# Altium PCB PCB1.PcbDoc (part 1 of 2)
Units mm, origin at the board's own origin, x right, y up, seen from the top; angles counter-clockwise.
Board outline 100 x 100 mm, 4 copper layers (Top Layer, Layer 1, Layer 2, Bottom Layer), stack 1.578 mm thick; 186 components, 85 nets, 396 pads, 143 vias.
Unrouted connection lines stored in the file: 19.
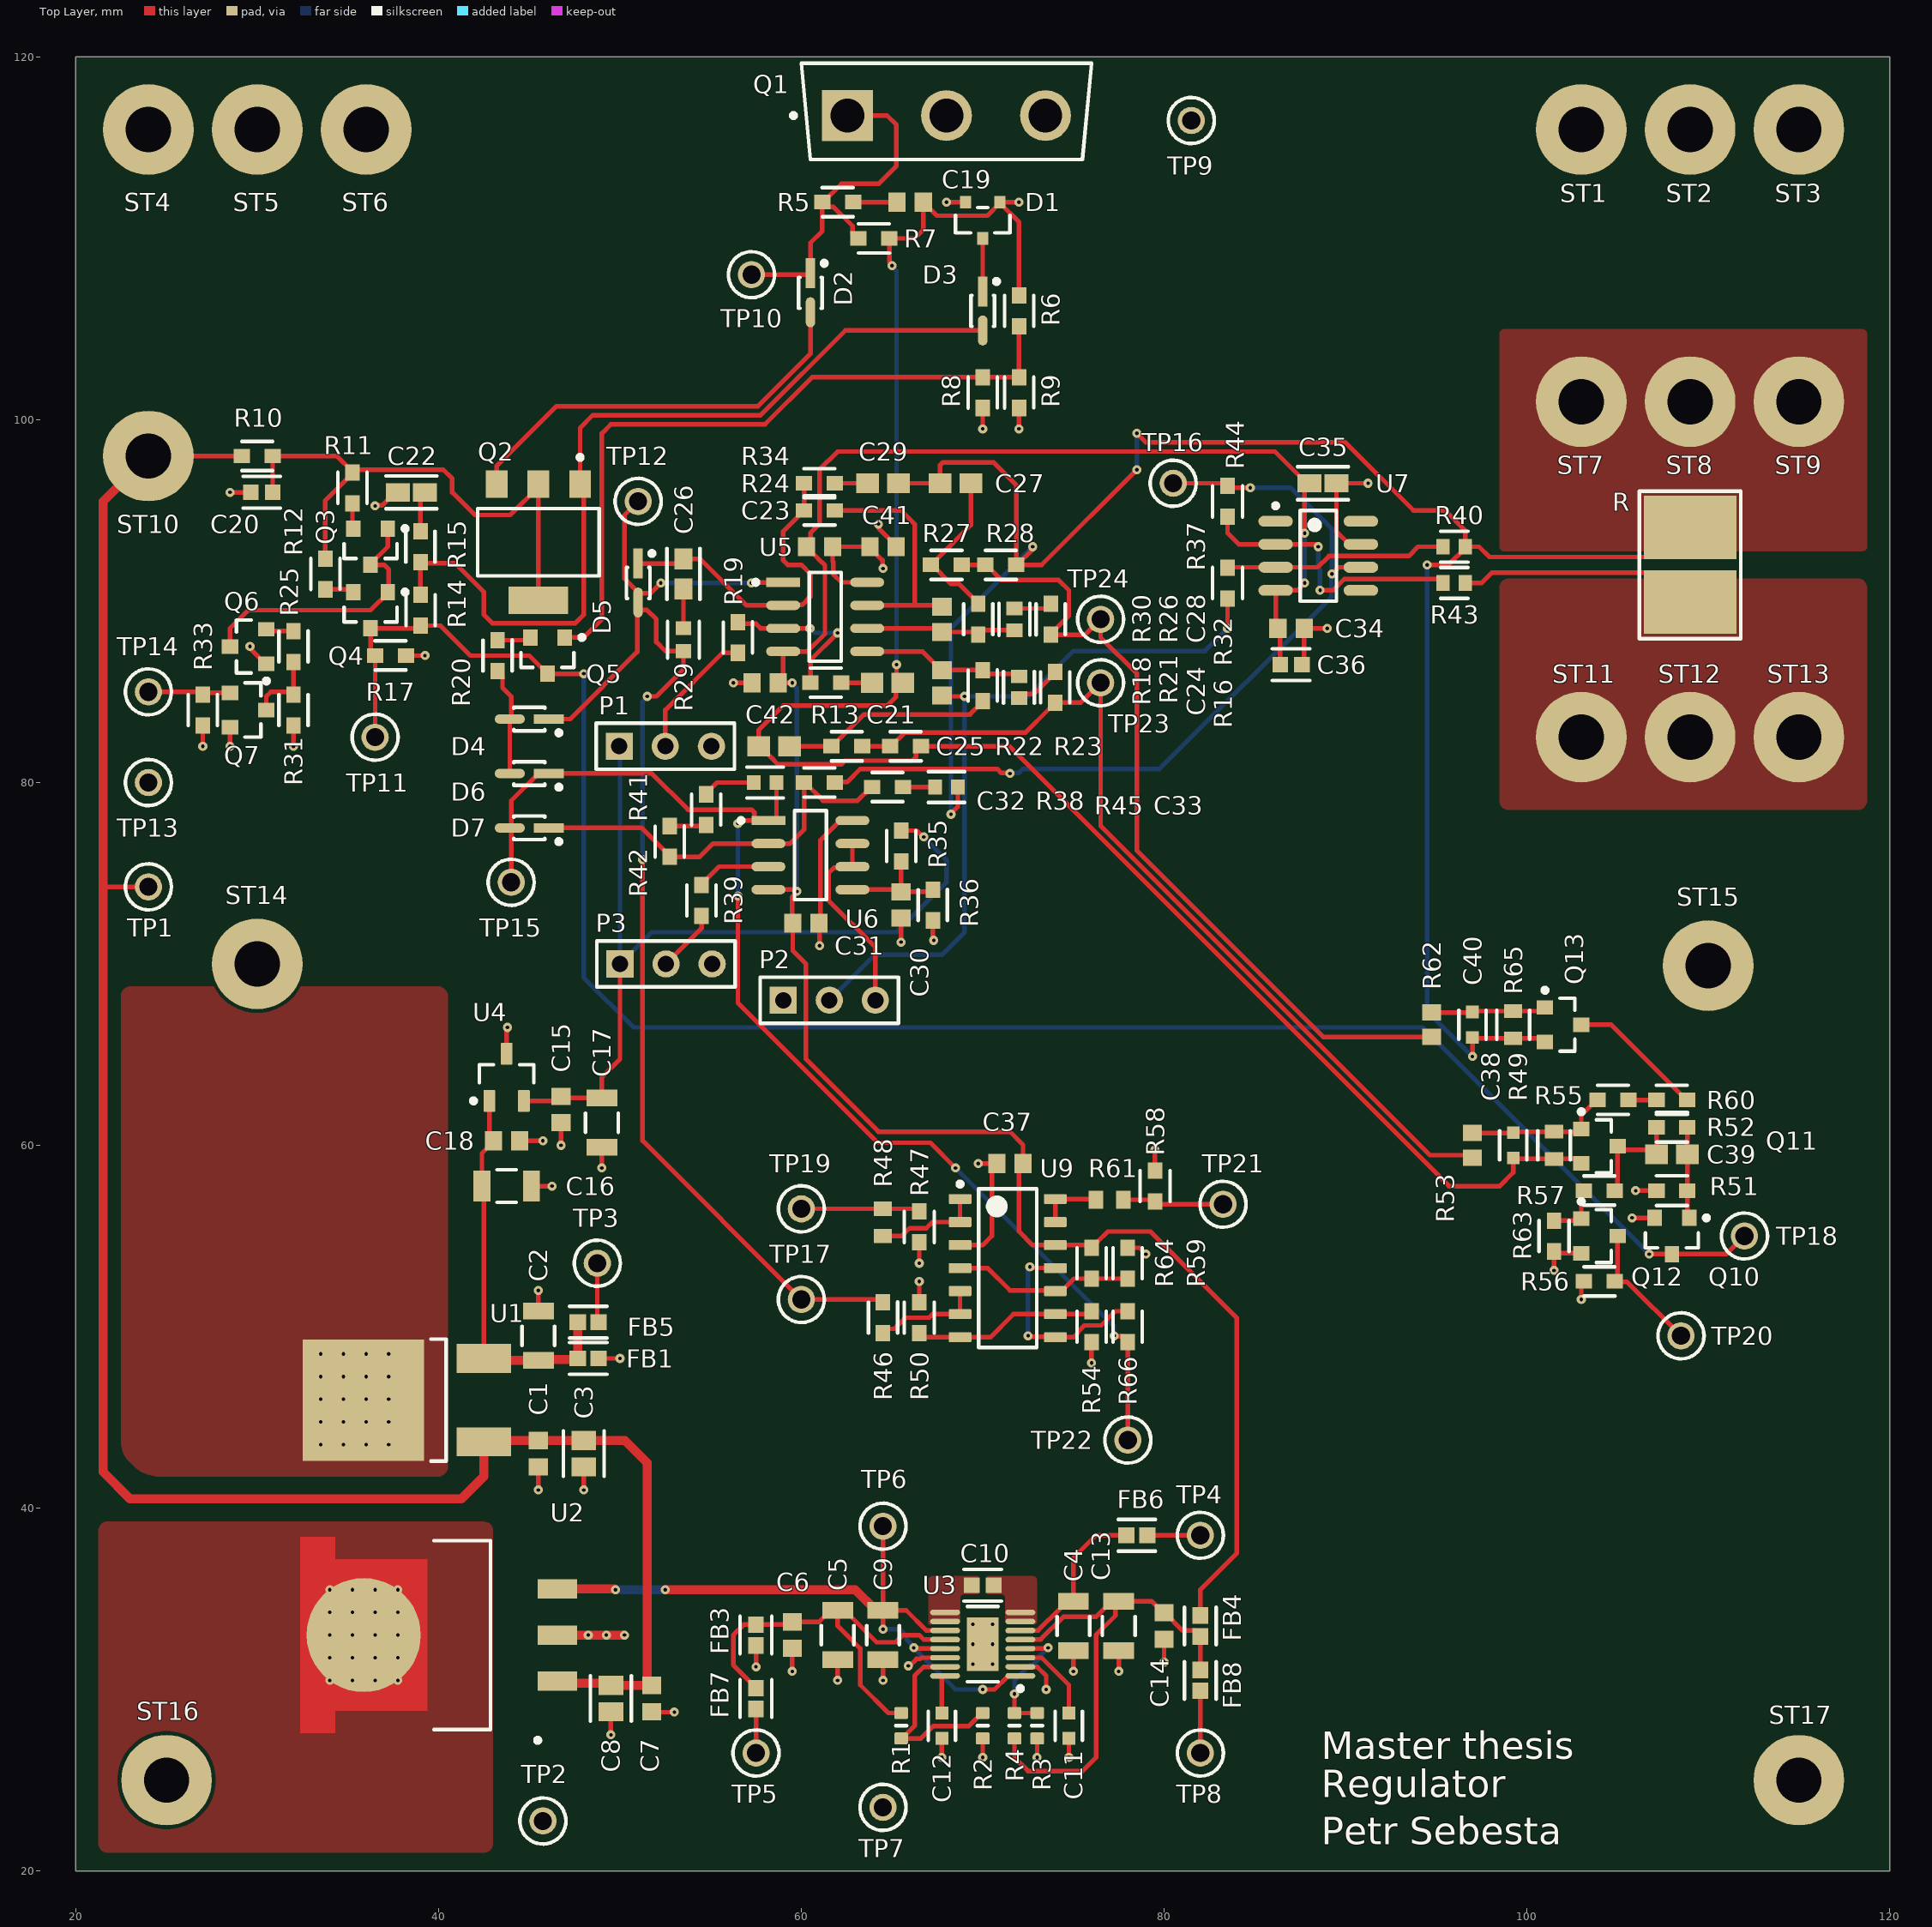
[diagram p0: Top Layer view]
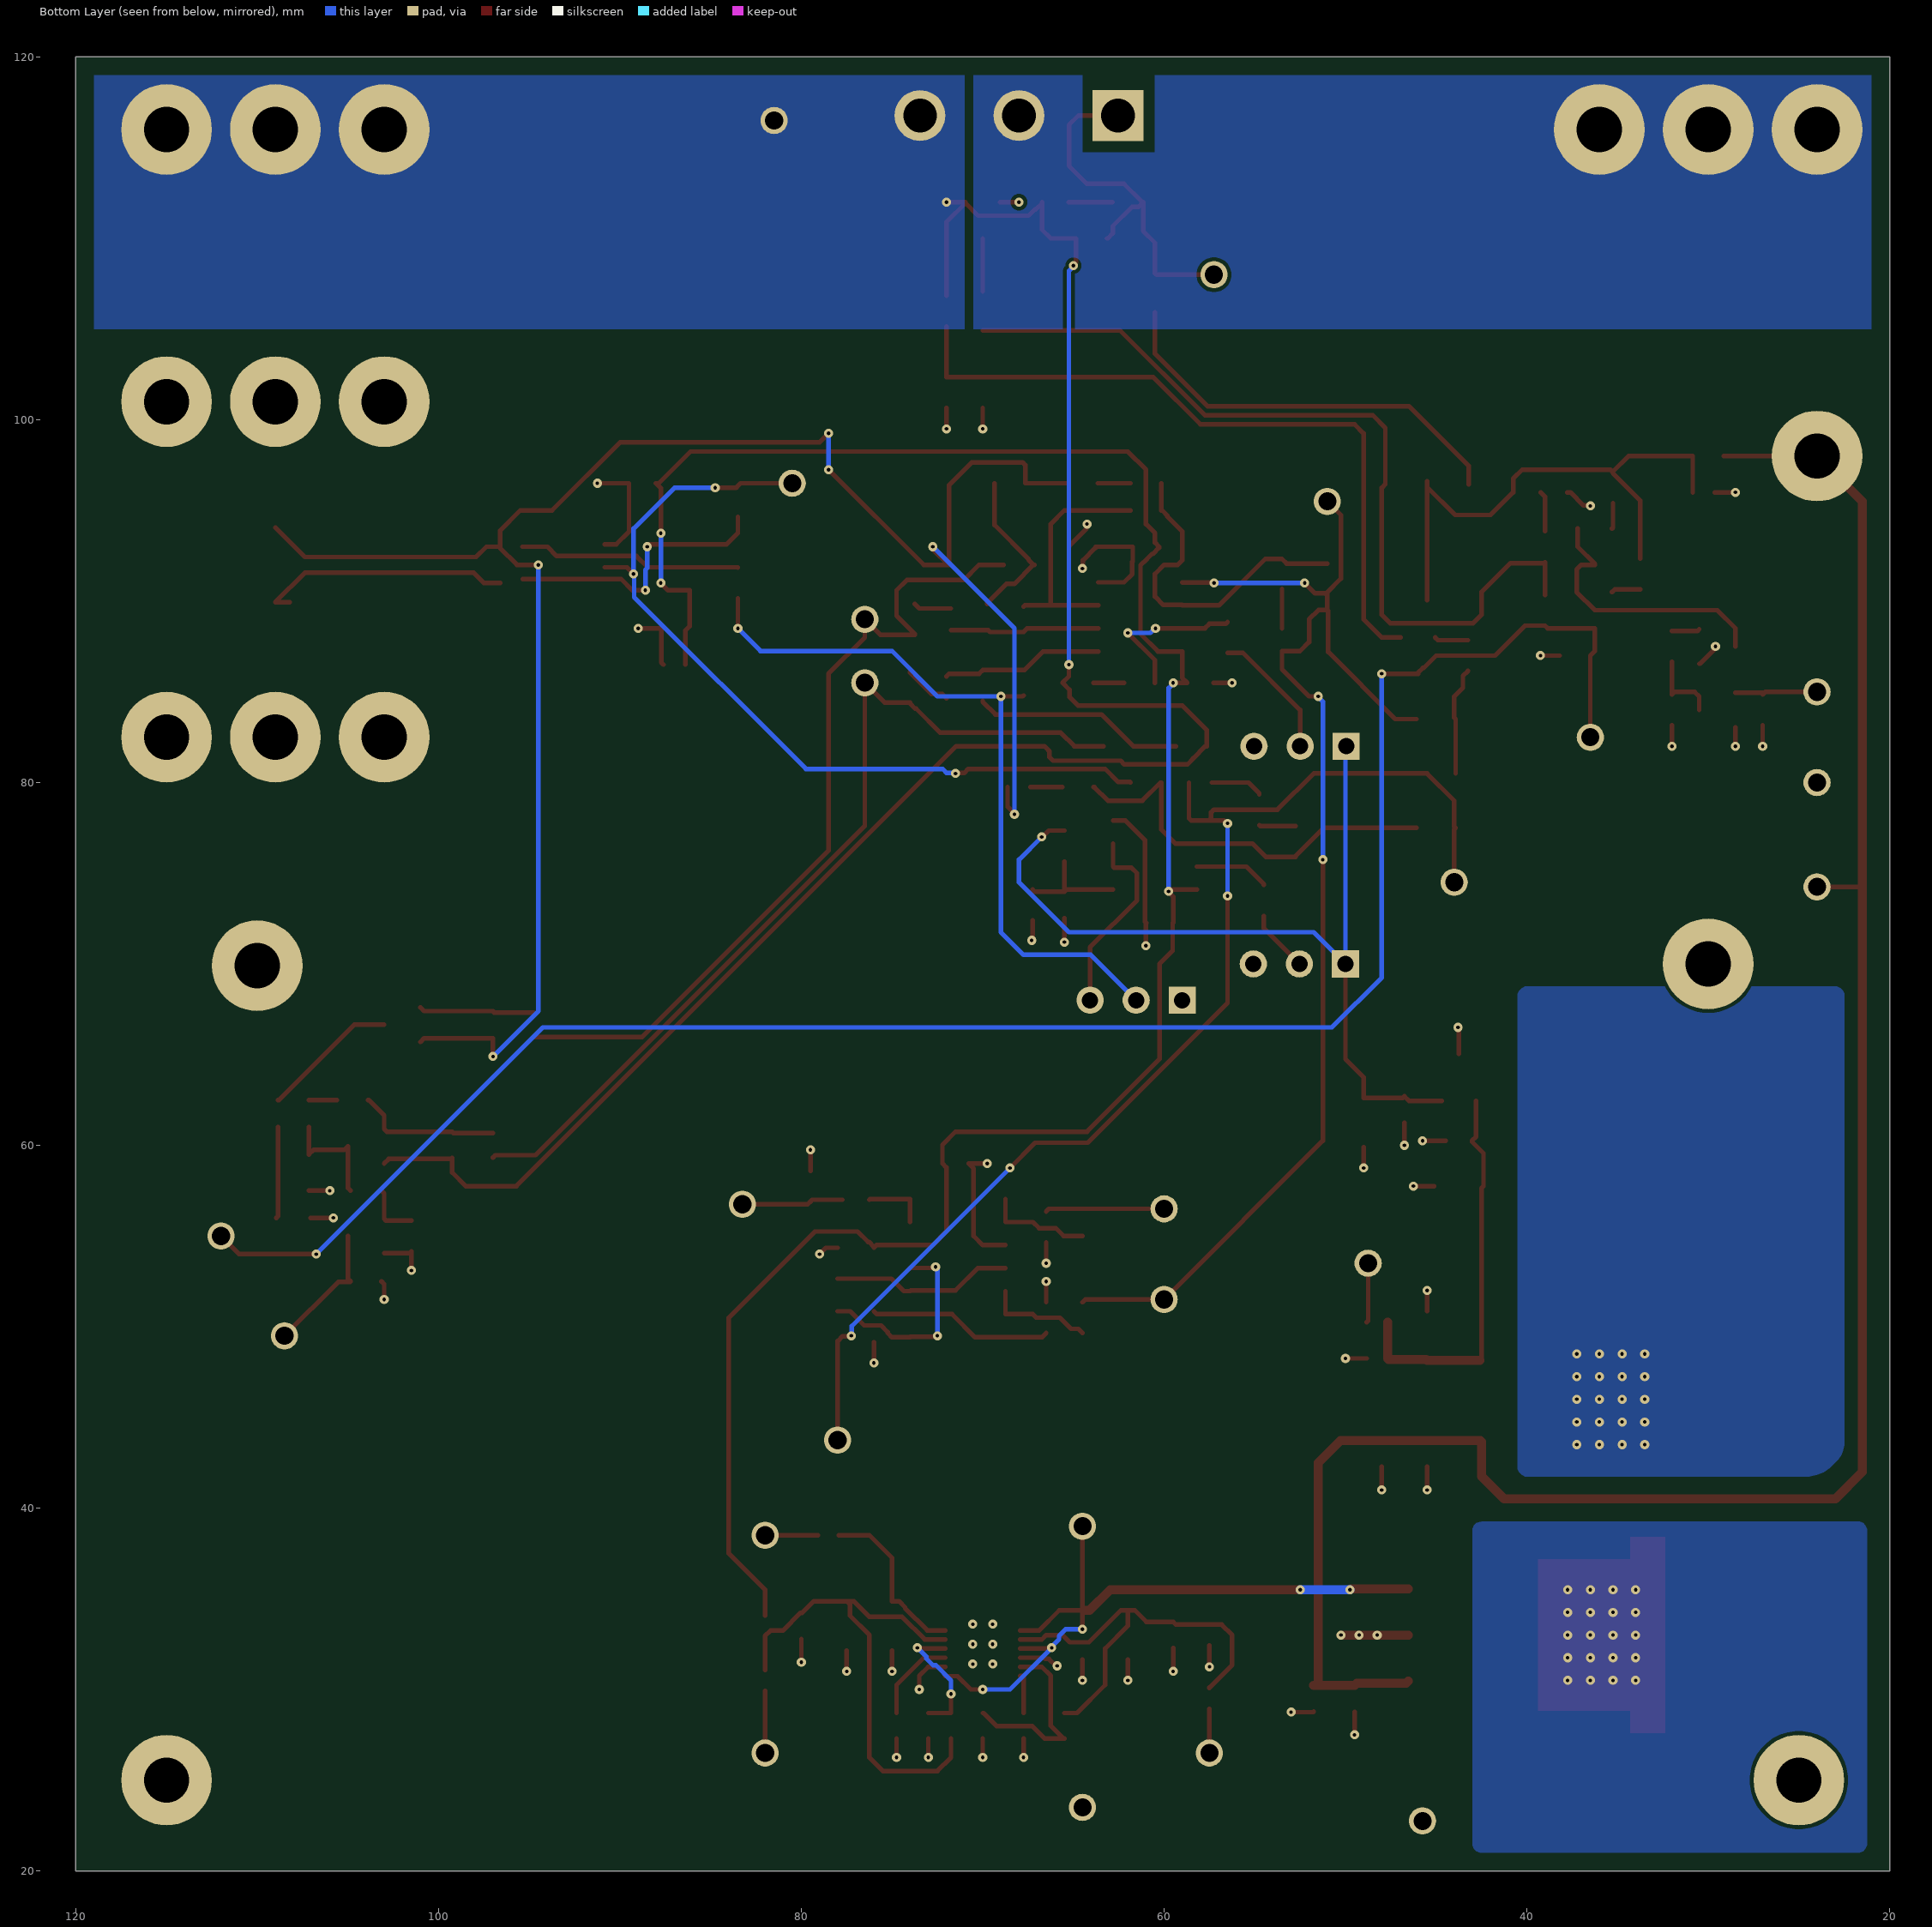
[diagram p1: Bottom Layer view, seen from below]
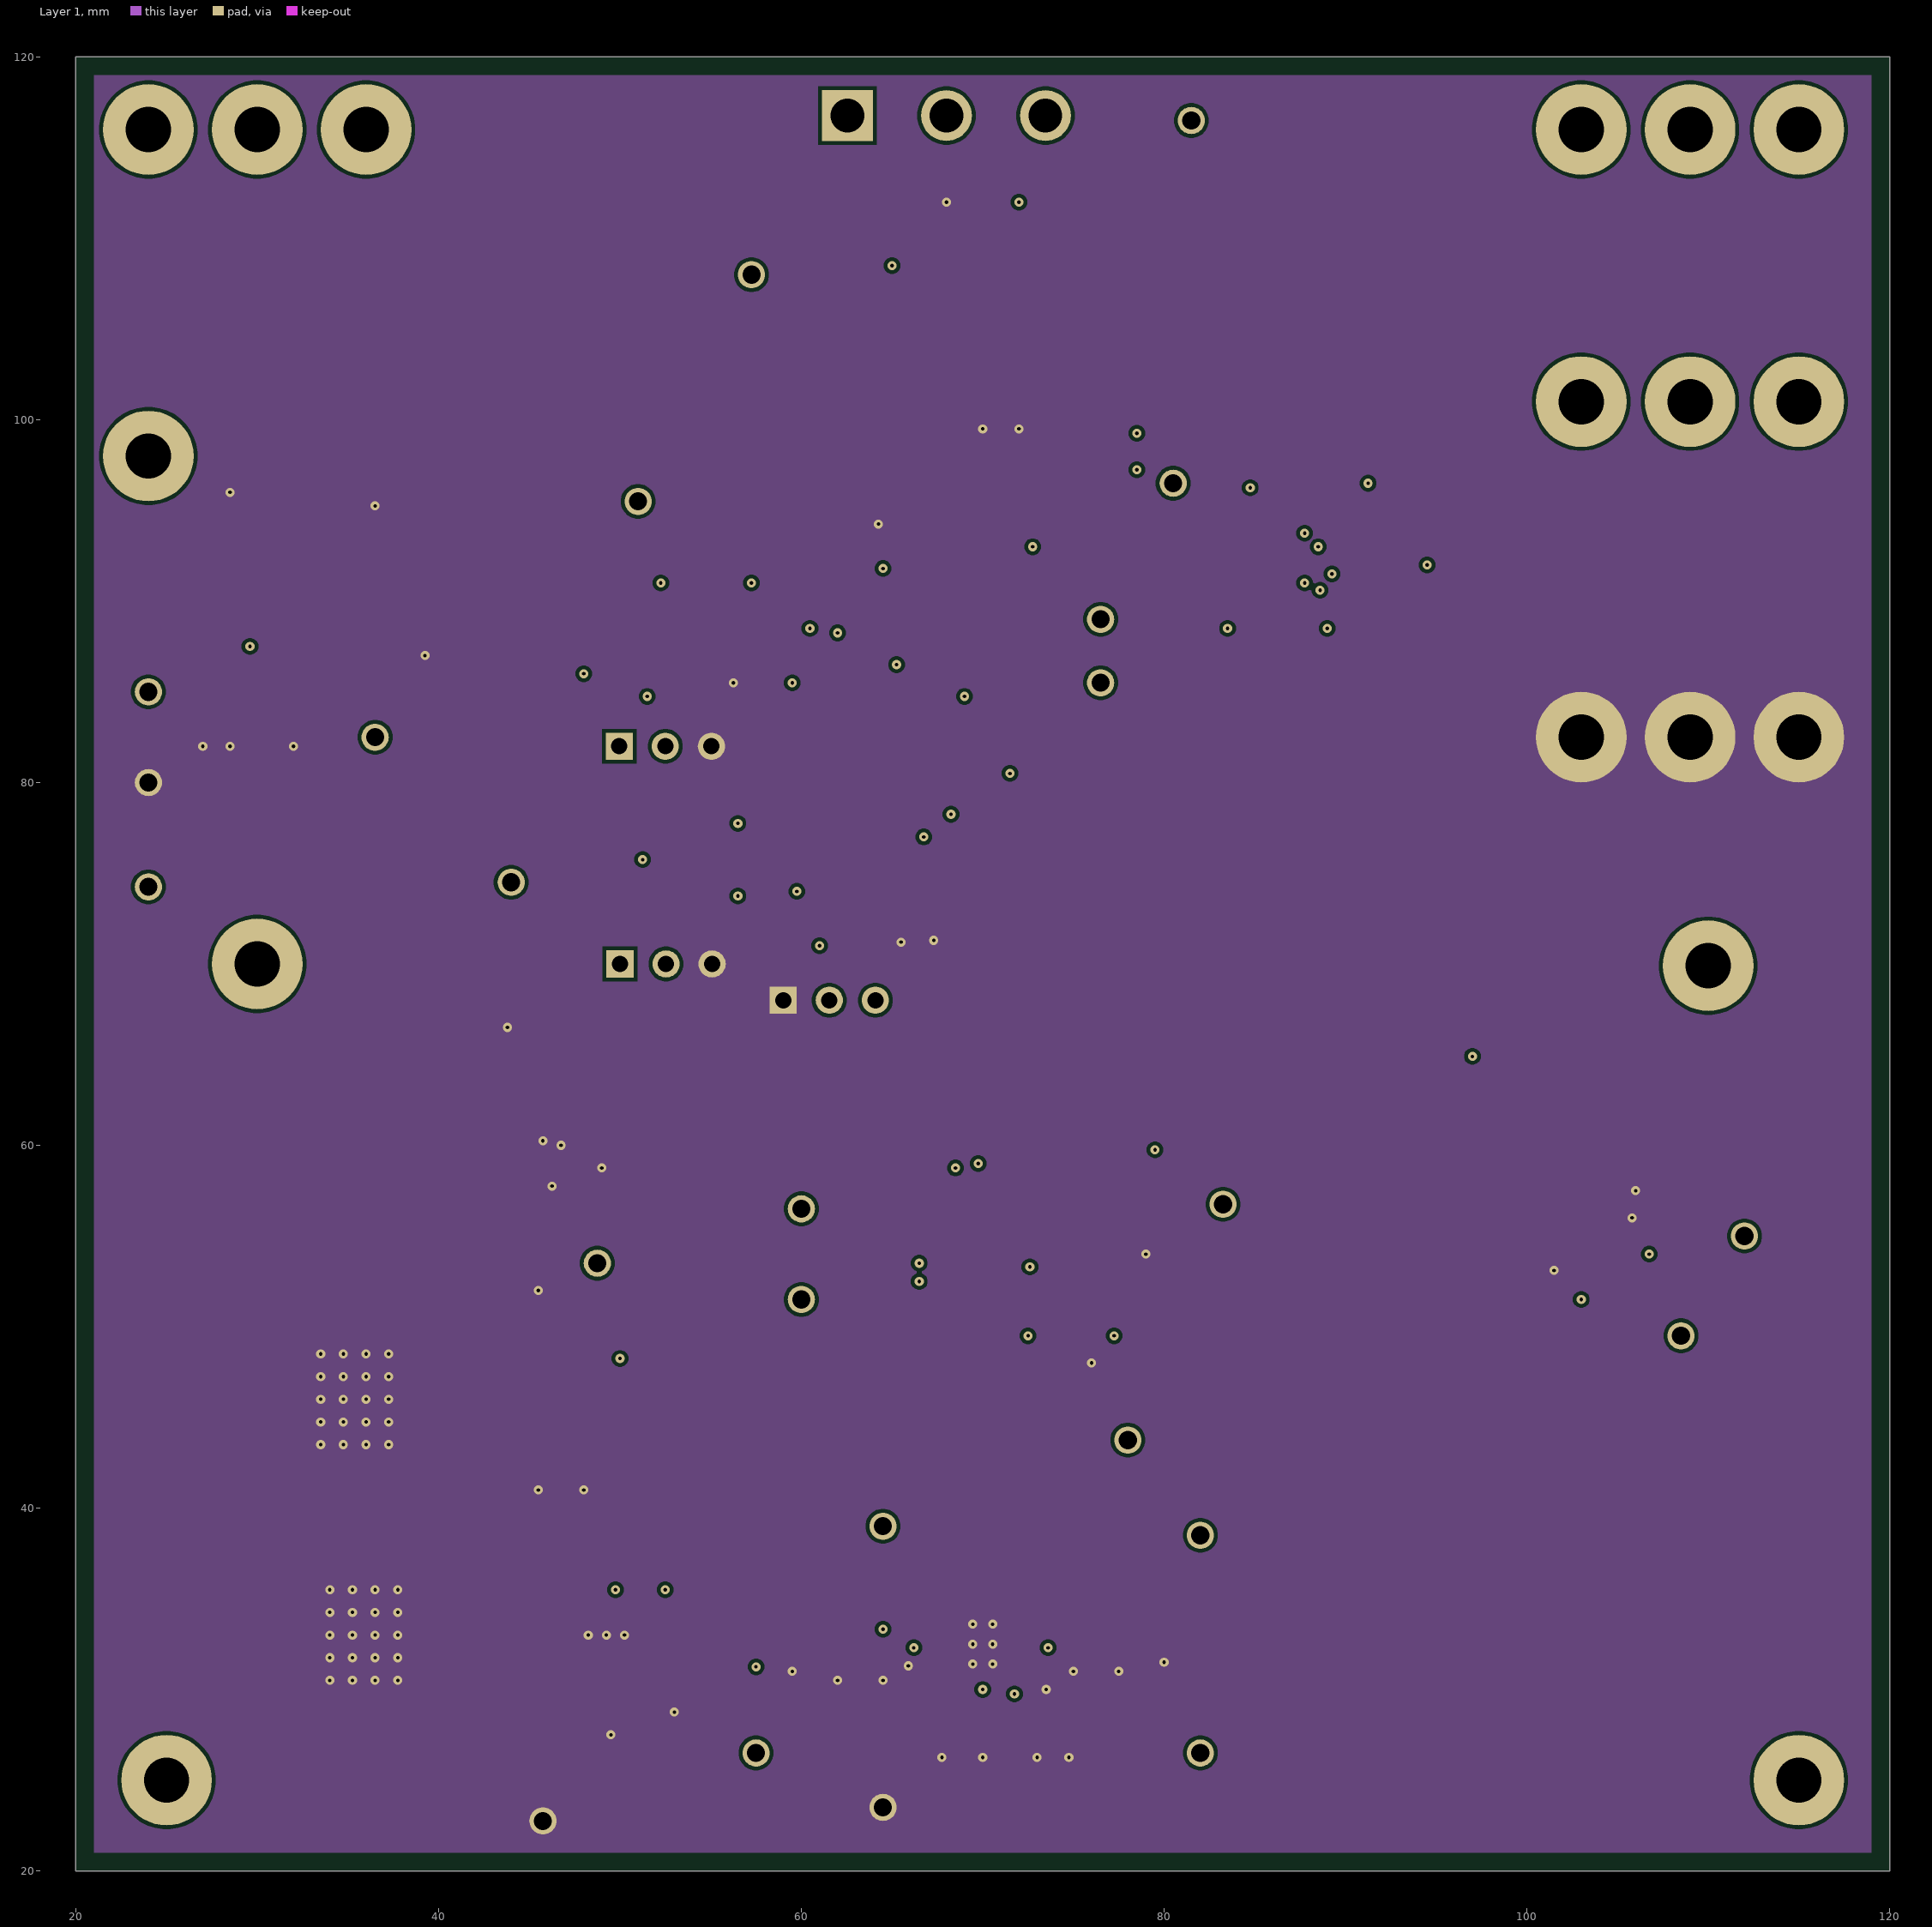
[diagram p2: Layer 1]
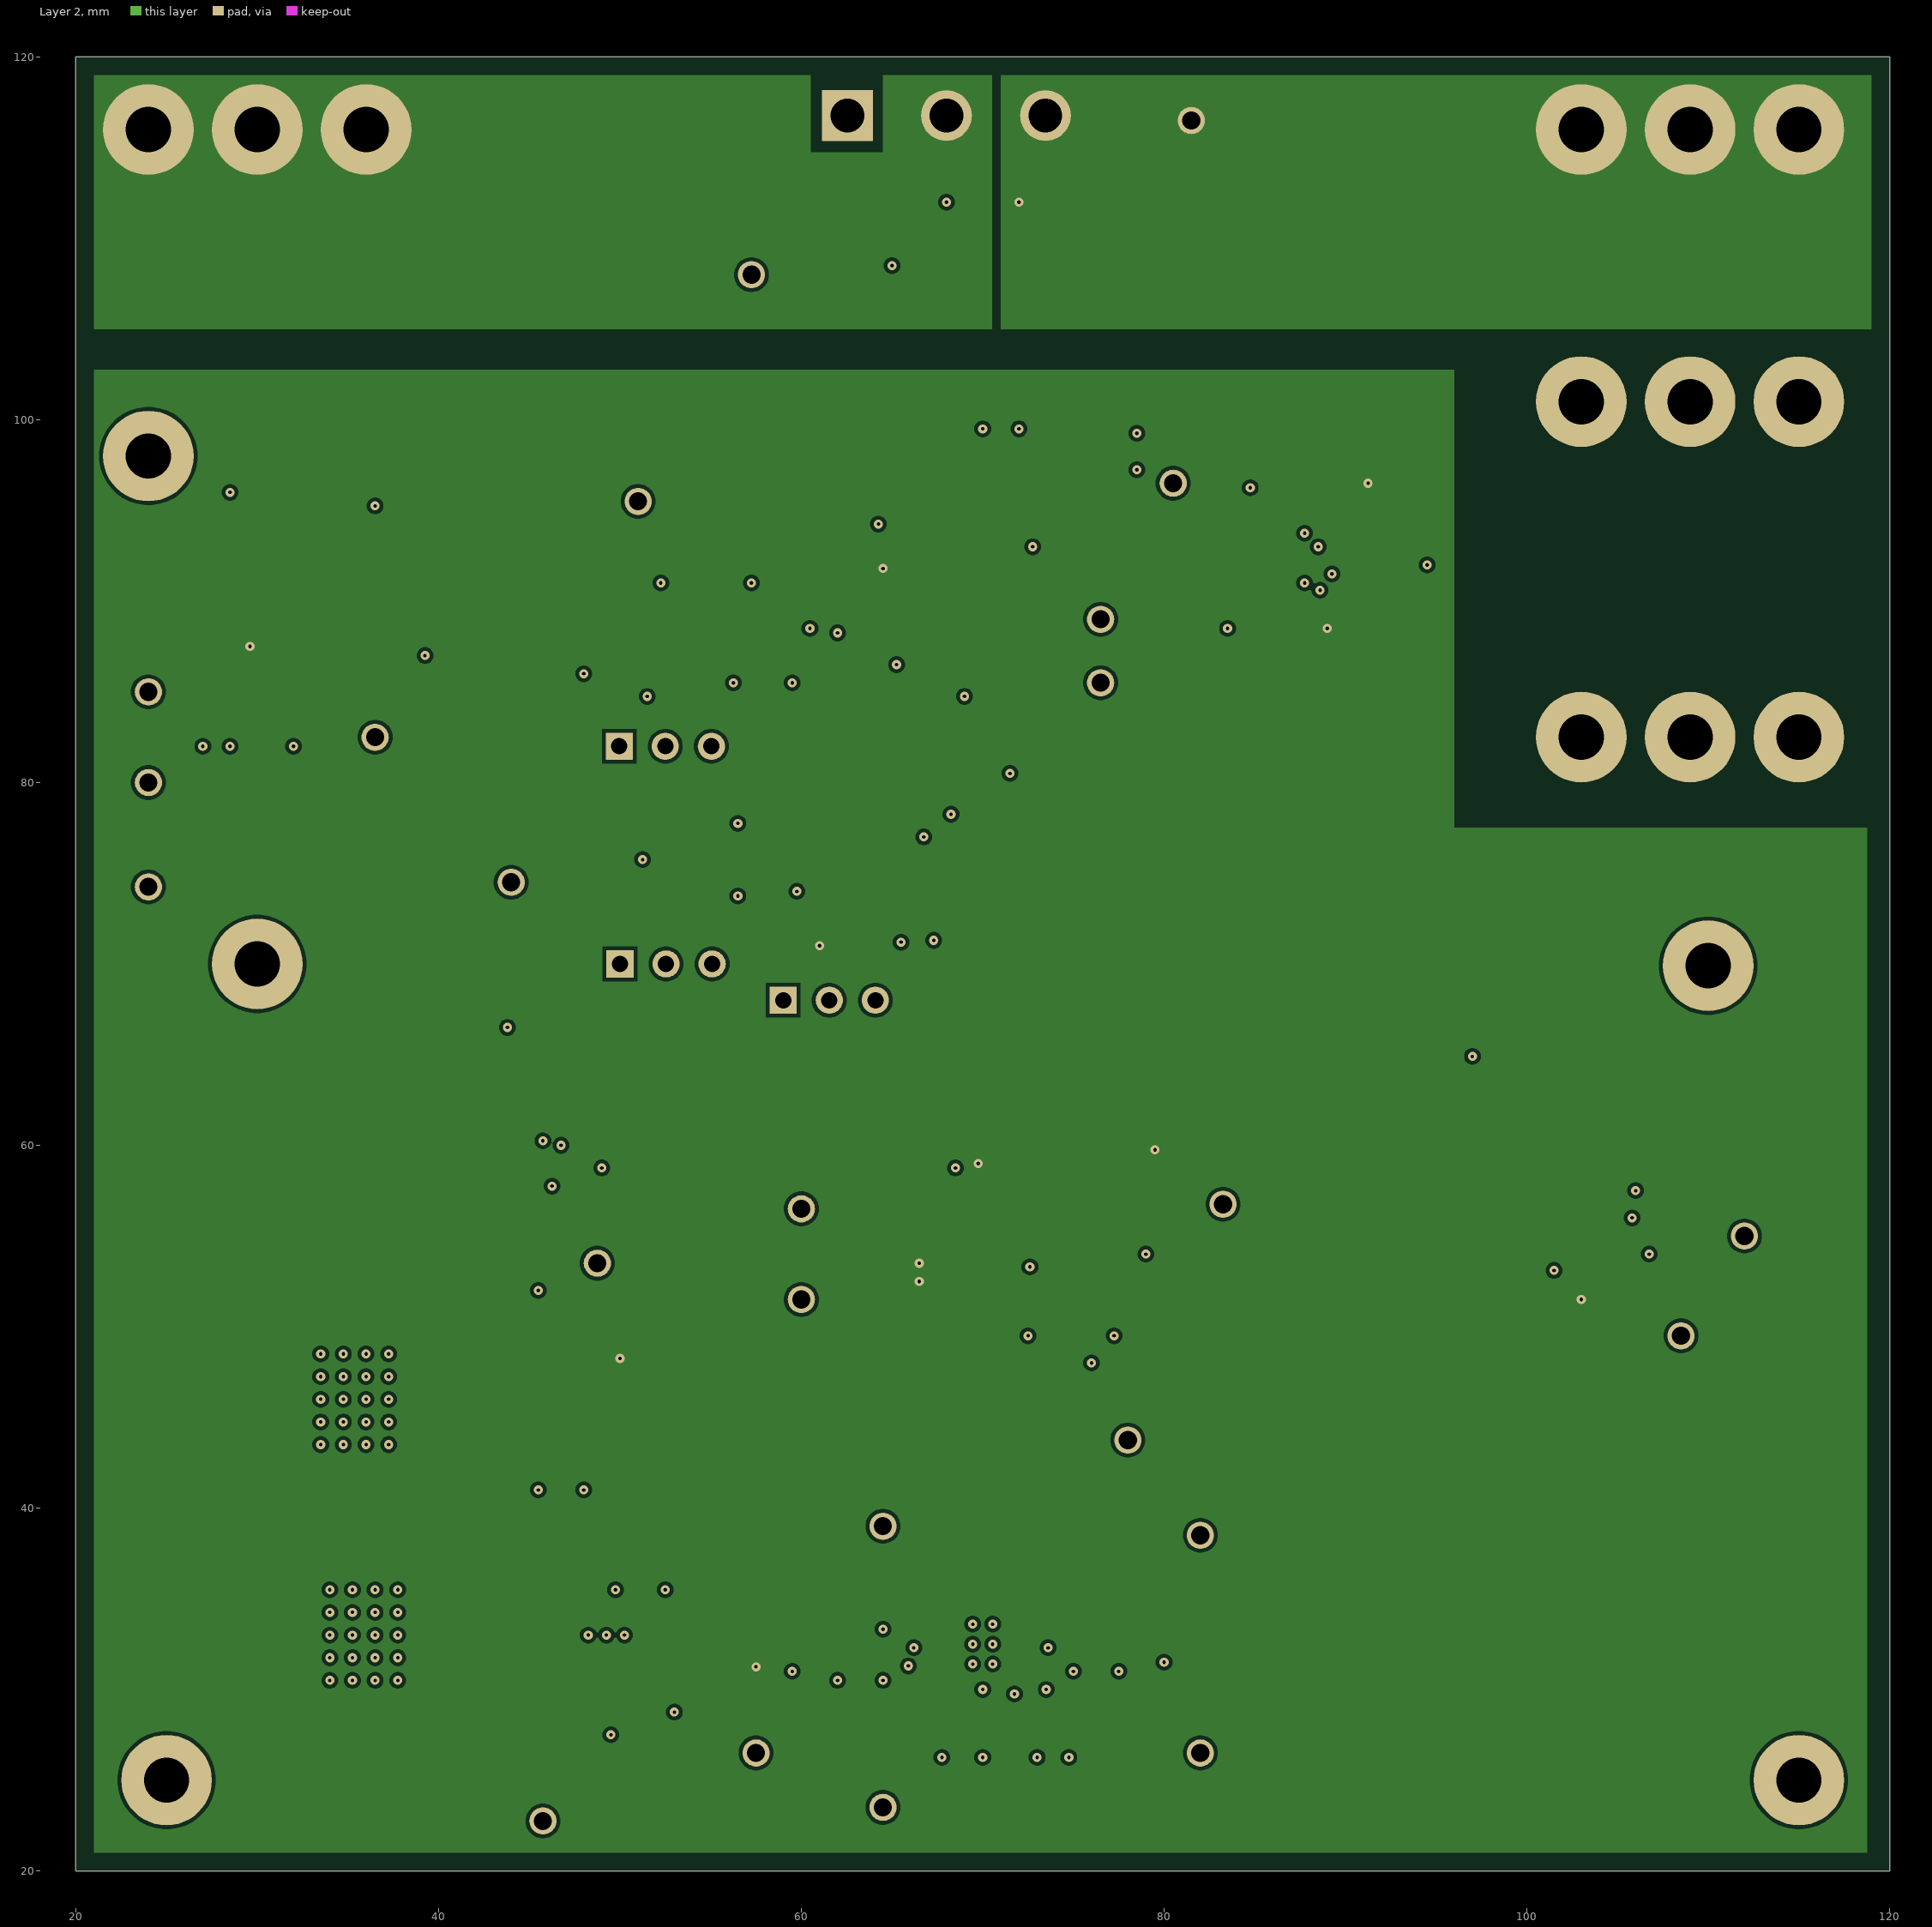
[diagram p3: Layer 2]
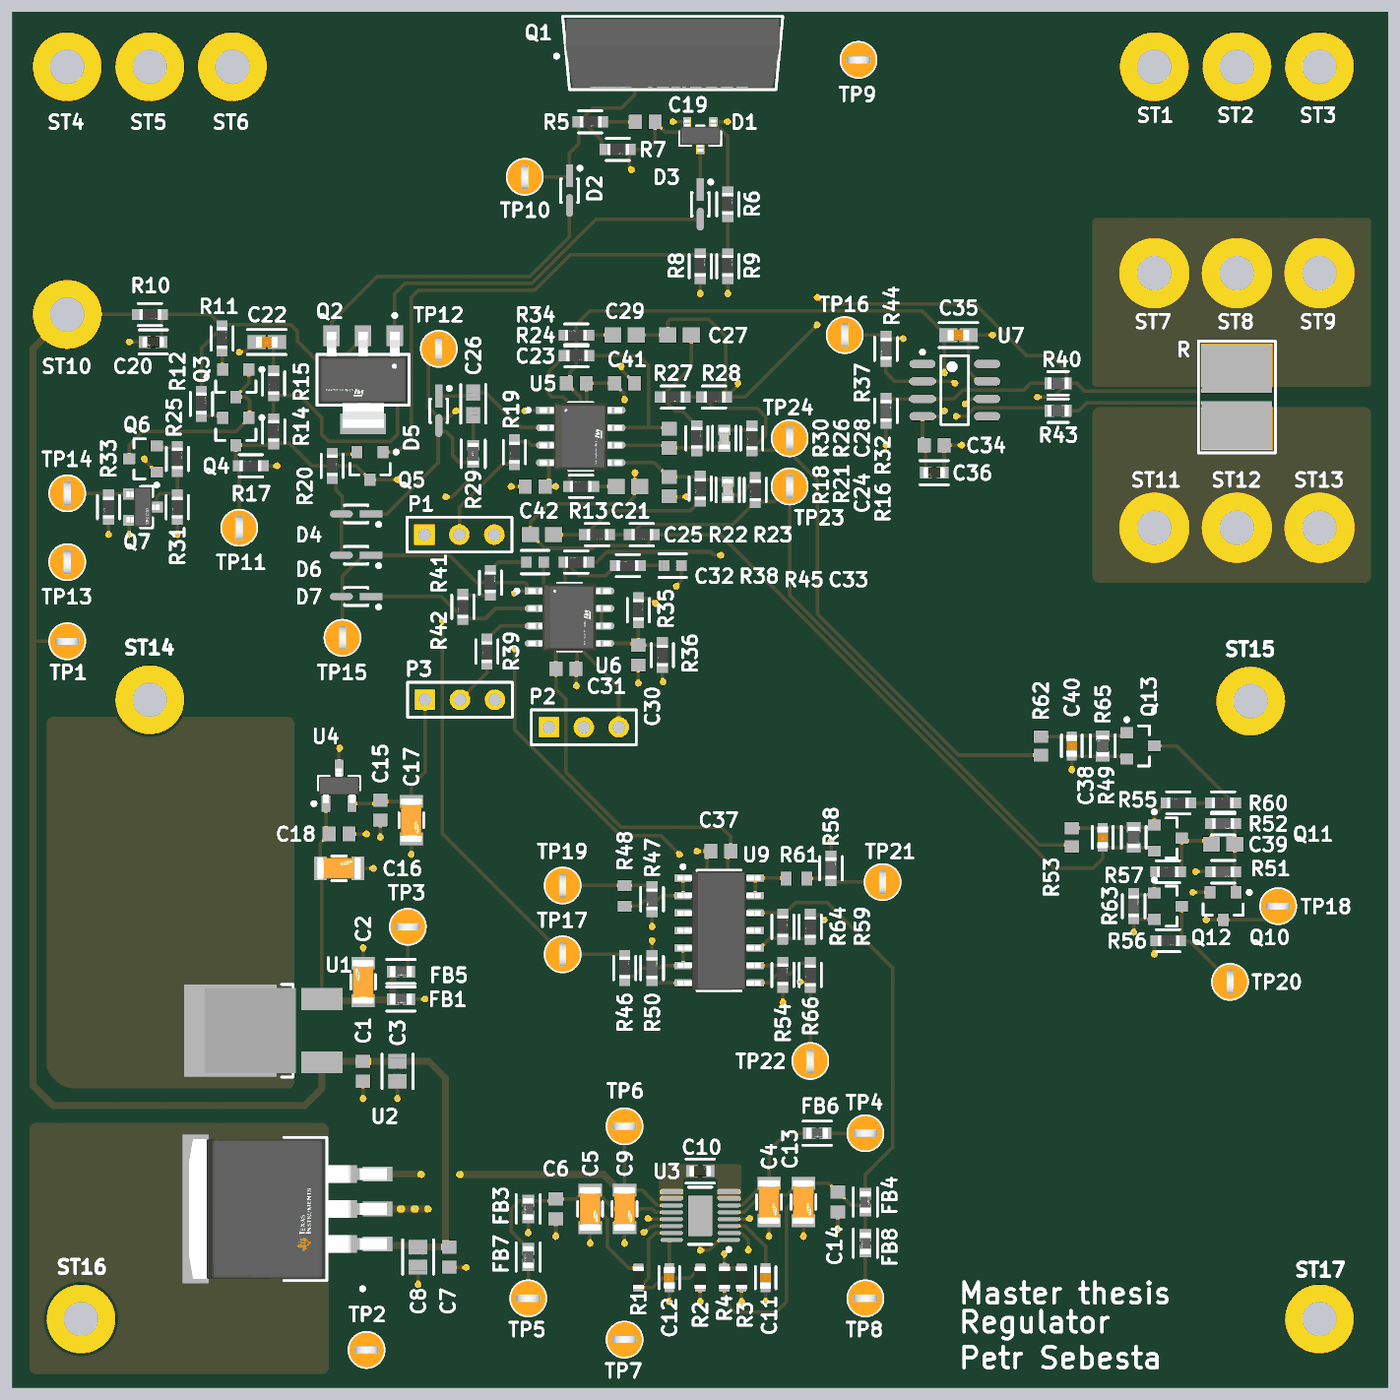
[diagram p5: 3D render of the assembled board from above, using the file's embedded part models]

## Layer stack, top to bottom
Top Solder: solder mask 0.0203, Solder Resist, Dk 3.8
Top Layer: signal copper 0.0356
Dielectric 2: prepreg 0.2104, PP-006, Dk 4.6
Layer 1: signal copper 0.0152
Dielectric 1: dielectric 1.056, FR-4, Dk 4.6
Layer 2: signal copper 0.0152
Dielectric 3: prepreg 0.2104, PP-006, Dk 4.6
Bottom Layer: signal copper 0.0356
Bottom Solder: solder mask 0.0203, Solder Resist, Dk 3.8

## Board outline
20,20 120,20 120,120 20,120

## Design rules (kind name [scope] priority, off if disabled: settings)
Clearance [All] p1: gap=0.2 ignorepadtopadclearanceinfootprint=FALSE except(0.128: SMDPad-SMDPad)
MinimumSolderMaskSliver [All] p1: minsoldermaskwidth=0.05
PolygonConnect PolygonConnect_1 [All vs IsNamedPolygon('NONET_L01_P-001') Or IsNamedPolygon('NONET_L01_P-001')] p1: connectstyle=Direct reliefconductorwidth=0.254 reliefentries=4 polygonreliefangle="90 Angle" airgapwidth=0.254
PolygonConnect [All] p2: connectstyle=Relief reliefconductorwidth=0.254 reliefentries=4 polygonreliefangle="90 Angle" airgapwidth=0.254
RoutingVias [All] p1: holewidth=0.2 width=0.5 viastyle="Through Hole" minholewidth=0.2 minwidth=0.5 maxholewidth=0.35 maxwidth=0.6 viatemplateguid#1={09E4A0CF-320E-4250-8A00-14222AEA9F8E} viatemplateguid#2={F598F4F2-577E-4066-8F44-7938A3B5318D} viatemplatename#1=v50h20 viatemplatename#2=v40h20
SilkToSilkClearance [All] p1: silktosilkclearance=0
SilkToSolderMaskClearance [IsPad] p1: minsilkscreentomaskgap=0 clearancetoexposedcopper=TRUE
SolderMaskExpansion [All] p1: expansion=0.05 istentingtop=FALSE
Width [All] p1: maxlimit=3 minlimit=0.254 preferedwidth=0.254
27 further rules are at their usual default settings.

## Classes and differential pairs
component class Support: C37 C38 C39 C40 Q10 Q11 Q12 Q13 R46 R47 R48 R49 R50 R51 R52 R53 R54 R55 R56 R57 R58 R59 R60 R61 R62 R63 R64 R65 R66 ST14 ST15 ST16 ST17 TP17 TP18 TP19 TP20 TP21 TP22 U9
component class Regulator: C19 C20 C21 C22 C23 C24 C25 C26 C27 C28 C29 C41 C42 D1 D2 D3 D4 D5 P1 Q1 Q2 Q3 Q4 Q5 Q6 Q7 R5 R6 R7 R8 R9 R10 R11 R12 R13 R14 R15 R16 R17 R18 R19 R20 R21 R22 R23 R24 R25 R26 R27 R28 R29 R30 R31 R32 R33 R34 ST1 ST2 ST3 ST4 ST5 ST6 ST7 ST8 ST9 ST10 ST11 ST12 ST13 TP9 TP10 TP11 TP12 TP13 TP14 TP23 TP24 U5
component class PowerSupply: C1 C2 C3 C4 C5 C6 C7 C8 C9 C10 C11 C12 C13 C14 C15 C16 C17 C18 FB1 FB3 FB4 FB5 FB6 FB7 FB8 R1 R2 R3 R4 TP1 TP2 TP3 TP4 TP5 TP6 TP7 TP8 U1 U2 U3 U4
component class ILoopAnd0.05V: C30 C31 C32 C33 C34 C35 C36 D6 D7 P2 P3 R R35 R36 R37 R38 R39 R40 R41 R42 R43 R44 R45 TP15 TP16 U6 U7

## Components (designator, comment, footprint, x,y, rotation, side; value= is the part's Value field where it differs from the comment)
C1 "CL10B104KB8NNNC" SAMS-C0603-2_M 45.5,43 r90 top
C2 "CL31B106KBHNNNE" FP-CL31B106KBHNNNE-MFG 45.5,49.5 r90 top value=10uF
C3 "CL21B105KBFNNNG" FP-CL21-IPC_C 48,43 r270 top
C4 "CL31B106KBHNNNE" FP-CL31B106KBHNNNE-MFG 75,33.5 r270 top value=10uF
C5 "CL31B106KBHNNNE" FP-CL31B106KBHNNNE-MFG 62,33 r270 top value=10uF
C6 "CL10B104KB8NNNC" SAMS-C0603-2_M 59.5,33 r90 top
C7 "CL10B104KB8NNNC" SAMS-C0603-2_M 51.75,29.5 r90 top
C8 "CL21B105KBFNNNG" FP-CL21-IPC_C 49.5,29.5 r270 top
C9 "CL31B106KBHNNNE" FP-CL31B106KBHNNNE-MFG 64.5,33 r270 top value=10uF
C10 "UMK107AB7105KA-T" FP-0603-L_1_6_0_15-W_0_8-IPC_C 70,35.75 r0 top
C11 "C1608X7R1H103M080AA" FP-C1608-080-0_1-MFG 74.75,28 r90 top
C12 "C1608X7R1H103M080AA" FP-C1608-080-0_1-MFG 67.75,28 r90 top
C13 "CL31B106KBHNNNE" FP-CL31B106KBHNNNE-MFG 77.5,33.5 r270 top value=10uF
C14 "CL10B104KB8NNNC" SAMS-C0603-2_M 80,33.5 r90 top
C15 "CL10B104KB8NNNC" SAMS-C0603-2_M 46.75,61.975 r90 top
C16 "CL31B106KBHNNNE" FP-CL31B106KBHNNNE-MFG 43.75,57.75 r0 top value=10uF
C17 "CL31B106KBHNNNE" FP-CL31B106KBHNNNE-MFG 49,61.25 r270 top value=10uF
C18 "CL10B104KB8NNNC" SAMS-C0603-2_M 43.75,60.25 r180 top
C19 "CL10B104KB8NNNC" SAMS-C0603-2_M 66,112 r0 top
C20 "UMK107AB7105KA-T" FP-0603-L_1_6_0_15-W_0_8-IPC_C 30.25,96 r180 top
C21 "06035C222KAT4A" CAPC1608X90X35ML15T15 64.75,85.5 r0 top value=2n2
C22 "C1608X7R1H103M080AA" FP-C1608-080-0_1-IPC_A 38.5,96 r0 top
C23 "CL10B104KB8NNNC" SAMS-C0603-2_M 61,93 r0 top
C24 "C0603C470M5HACTU" FP-C0603C-CF-MFG 72,85.25 r270 top value="47 pF"
C25 "06035C222KAT4A" CAPC1608X90X35ML15T15 58.5,82 r180 top value=2n2
C26 "CL10B121KB8NNNC" FP-CL10-IPC_A 53.5,91.5 r90 top
C27 "06035C222KAT4A" CAPC1608X90X35ML15T15 68.5,96.5 r180 top value=2n2
C28 "C0603C470M5HACTU" FP-C0603C-CF-MFG 71.75,89 r90 top value="47 pF"
C29 "06035C222KAT4A" CAPC1608X90X35ML15T15 64.5,96.5 r0 top value=2n2
C30 "CL10B104KB8NNNC" SAMS-C0603-2_M 65.5,73.25 r90 top
C31 "CL10B104KB8NNNC" SAMS-C0603-2_M 60.25,72.25 r0 top
C32 "CL10B102KB8WPNC" FP-CL10-IPC_C 58,80 r180 top
C33 "CL10B102KB8WPNC" FP-CL10-IPC_C 68,79.75 r0 top
C34 "CL10B104KB8NNNC" SAMS-C0603-2_M 87,88.5 r0 top
C35 "C1608X7R1H103M080AA" FP-C1608-080-0_1-IPC_A 88.759,96.5 r0 top
C36 "UMK107AB7105KA-T" FP-0603-L_1_6_0_15-W_0_8-IPC_C 87,86.5 r180 top
C37 "CL10B104KB8NNNC" SAMS-C0603-2_M 71.5,59 r180 top
C38 "C1608X7R1H103M080AA" FP-C1608-080-0_1-MFG 99.25,60 r270 top
C39 "06035C222KAT4A" CAPC1608X90X35ML15T15 108,59.5 r0 top value=2n2
C40 "C1608X7R1H103M080AA" FP-C1608-080-0_1-MFG 97,66.65 r90 top
C41 "CL10B104KB8NNNC" SAMS-C0603-2_M 64.5,93 r180 top
C42 "CL10B104KB8NNNC" SAMS-C0603-2_M 58,85.5 r180 top
D1 "BZX84-C15,215" FP-SOT23-MFG#1 70,111 r270 top
D2 "BAS316,115" FP-SOD323-IPC_A 60.5,107 r270 top
D3 "BAS316,115" FP-SOD323-IPC_A 70,106 r270 top
D4 "BAS316,115" FP-SOD323-IPC_A 45,83.5 r180 top
D5 "BAS316,115" FP-SOD323-IPC_A 51,91 r270 top
D6 "BAS316,115" FP-SOD323-IPC_A 45,80.5 r180 top
D7 "BAS316,115" FP-SOD323-IPC_A 45,77.5 r180 top
FB1 "BLM18PG600SH1D" FP-BLM18-0_15-t0_8-IPC_C 48.25,48.25 r0 top
FB3 "BLM18PG600SH1D" FP-BLM18-0_15-t0_8-IPC_C 57.5,33 r270 top
FB4 "BLM18PG600SH1D" FP-BLM18-0_15-t0_8-IPC_C 82,33.5 r90 top
FB5 "BLM18PG600SH1D" FP-BLM18-0_15-t0_8-IPC_C 48.25,50.25 r0 top
FB6 "BLM18PG600SH1D" FP-BLM18-0_15-t0_8-IPC_C 78.5,38.5 r0 top
FB7 "BLM18PG600SH1D" FP-BLM18-0_15-t0_8-IPC_C 57.5,29.5 r270 top
FB8 "BLM18PG600SH1D" FP-BLM18-0_15-t0_8-IPC_C 82,30.5 r270 top
P1 "Header 3" HDR1X3 49.96,82 r0 top
P2 "Header 3" HDR1X3 59,68 r0 top
P3 "Header 3" HDR1X3 50,70 r0 top
Q1 "IRFP250NPBF" FP-PG-TO247-3-MFG 68,117 r90 top
Q2 "BCP56-16" FP-SOT-223-P008-MFG 45.5,93.25 r270 top
Q3 "MMBT5401LT1G" ONSC-SOT-23-3-318-08_V 36.25,93 r270 top
Q4 "MMBT5401LT1G" ONSC-SOT-23-3-318-08_V 36.25,89.5 r270 top
Q5 "MMBT5551LT1G" ONSC-SOT-23-3-318-08_V 46,87 r270 top
Q6 "MMBT5551LT1G" ONSC-SOT-23-3-318-08_V 29.5,87.5 r180 top
Q7 "2N7002-7-F" FP-SOT23-MFG#2 29.5,84 r0 top
Q10 "MMBT5551LT1G" ONSC-SOT-23-3-318-08_V 108,55 r270 top
Q11 "MMBT5401LT1G" ONSC-SOT-23-3-318-08_V 104,59.95 r0 top
Q12 "MMBT5551LT1G" ONSC-SOT-23-3-318-08_V 104,55 r0 top
Q13 "MMBT5551LT1G" ONSC-SOT-23-3-318-08_V 102,66.65 r0 top
R "WSHM2818R0200FEA" WSHM2818R0200FEA 109,92 r270 top value=0.02R
R1 "SFR03EZPJ274" RESC0603(1608)_L 65.5,28 r90 top value=270k
R2 "SFR03EZPJ823" RESC0603(1608)_L 70,28 r90 top value=82k
R3 "SFR03EZPJ823" RESC0603(1608)_L 73,28 r270 top value=82k
R4 "SFR03EZPJ274" RESC0603(1608)_L 71.75,28 r90 top value=270k
R5 "RT0603FRE0710KL" FP-RT0603-MFG 62,112 r0 top value=10KΩ
R6 "RT0603DRE0716KL" FP-RT0603-MFG 72,106 r90 top value=16KΩ
R7 "RT0603FRE071KL" FP-RT0603-MFG 64,110 r0 top value=1KΩ
R8 "RT0603DRE07750RL" FP-RT0603-MFG 70,101.5 r90 top value=750Ω
R9 "RT0603FRE072K2L" FP-RT0603-MFG 72,101.5 r90 top value=2.2KΩ
R10 "RT0603FRE0710RL" FP-RT0603-MFG 30,98 r0 top value=10Ω
R11 "RT0603FRE07220RL" FP-RT0603-MFG 35.25,96.25 r90 top value=220Ω
R12 "RT0603FRE07220RL" FP-RT0603-MFG 33.75,91.5 r90 top value=220Ω
R13 "RT0603FRE07220RL" FP-RT0603-MFG 61.35,85.5 r180 top value=220Ω
R14 "RT0603FRE07100RL" FP-RT0603-MFG 39,89.5 r90 top value=100Ω
R15 "RT0603FRE07470RL" FP-RT0603-MFG 39,93 r270 top value=470Ω
R16 "RT0603FRE0710KL" FP-RT0603-MFG 74,85.25 r270 top value=10KΩ
R17 "RT0603FRE0751KL" FP-RT0603-MFG 37.35,87 r180 top value=51KΩ
R18 "ERA3AEB752V" RESC1608X55X30ML20T20 67.75,85.5 r270 top value=7k5
R19 "RT0603FRE0710KL" FP-RT0603-MFG 56.5,88 r270 top value=10KΩ
R20 "RT0603FRE07470RL" FP-RT0603-MFG 43.25,87 r90 top value=470Ω
R21 "RT0603BRD07100KL" FP-RT0603-MFG 70,85.35 r270 top value=100KΩ
R22 "RT0603BRD0724KL" FP-RT0603-MFG 62.5,82 r0 top value=24KΩ
R23 "RT0603BRD072K2L" FP-RT0603-MFG 65.75,82 r0 top value=2.2KΩ
R24 "RT0603FRE0710KL" FP-RT0603-MFG 61,95 r0 top value=10KΩ
R25 "RT0603FRE071K8L" FP-RT0603-MFG 32,87.5 r90 top value=1.8KΩ
R26 "RT0603BRD07100KL" FP-RT0603-MFG 69.75,89 r90 top value=100KΩ
R27 "RT0603BRD0724KL" FP-RT0603-MFG 68,92 r0 top value=24KΩ
R28 "RT0603BRD072K2L" FP-RT0603-MFG 71,92 r0 top value=2.2KΩ
R29 "CRG0603ZR" FP-CRG0603-IPC_C 53.5,87.873 r90 top
R30 "ERA3AEB752V" RESC1608X55X30ML20T20 67.75,89 r270 top value=7k5
R31 "0R" FP-RT0603-MFG 32,84 r270 top
R32 "RT0603FRE0710KL" FP-RT0603-MFG 73.75,89 r270 top value=10KΩ
R33 "RT0603FRE07100KL" FP-RT0603-MFG 27,84 r270 top value=100KΩ
R34 "RT0603FRE07220RL" FP-RT0603-MFG 61,96.5 r180 top value=220Ω
R35 "RT0603FRE0710KL" FP-RT0603-MFG 65.5,76.5 r90 top value=10KΩ
R36 "RT0603FRE07220RL" FP-RT0603-MFG 67.25,73.25 r270 top value=220Ω
R37 "AC0603FR-07976RL" FP-AC0603-MFG 83.5,91 r90 top
R38 "RT0603FRE0710KL" FP-RT0603-MFG 61,80 r180 top value=10KΩ
R39 "RT0603BRD072K2L" FP-RT0603-MFG 54.5,73.5 r270 top value=2.2KΩ
R40 "CRCW060382R0FKEA" FP-CRCW0603-e3-IPC_C 96,93 r0 top
R41 "RT0603FRE0710KL" FP-RT0603-MFG 54.75,78.5 r90 top value=10KΩ
R42 "RT0603FRE071KL" FP-RT0603-MFG 52.75,76.75 r270 top value=1KΩ
R43 "CRCW060382R0FKEA" FP-CRCW0603-e3-IPC_C 96,91 r0 top
R44 "AC0603FR-07976RL" FP-AC0603-MFG 83.5,95.5 r270 top
R45 "RT0603FRE0710KL" FP-RT0603-MFG 64.75,79.75 r180 top value=10KΩ
R46 "RT0603FRE0710KL" FP-RT0603-MFG 64.5,50.5 r90 top value=10KΩ
R47 "AC0603FR-075K1L" FP-AC0603-MFG 66.5,55.5 r270 top
R48 "RC0603FR-075K6L" RESC1608X55X25ML10T15 64.5,55.75 r270 top
R49 "CRCW0603330RFKEA" FP-CRCW0603-e3-MFG 101.5,60 r270 top
R50 "AC0603FR-0747K5L" FP-AC0603-MFG 66.5,50.5 r90 top
R51 "AC0603FR-0747K5L" FP-AC0603-MFG 108,57.5 r0 top
R52 "AC0603FR-0747K5L" FP-AC0603-MFG 108,61 r0 top
R53 "CRCW0603750RJNEA" RESC1609X50X30ML10T20 97,60 r90 top value=750R
R54 "RT0603BRD072K2L" FP-RT0603-MFG 76,50 r90 top value=2.2KΩ
R55 "RT0603BRD072K2L" FP-RT0603-MFG 104.75,62.5 r180 top value=2.2KΩ
R56 "RT0603FRE0710KL" FP-RT0603-MFG 104,52.5 r0 top value=10KΩ
R57 "RT0603FRE0710KL" FP-RT0603-MFG 104,57.5 r180 top value=10KΩ
R58 "AC0603FR-075K1L" FP-AC0603-MFG 79.5,57.75 r90 top
R59 "RT0603FRE0710KL" FP-RT0603-MFG 78,53.5 r270 top value=10KΩ
R60 "RT0603FRE071KL" FP-RT0603-MFG 108,62.5 r180 top value=1KΩ
R61 "RC0603FR-075K6L" RESC1608X55X25ML10T15 77,57 r180 top
R62 "CRCW0603750RJNEA" RESC1609X50X30ML10T20 94.75,66.65 r270 top value=750R
R63 "AC0603FR-0747K5L" FP-AC0603-MFG 101.5,55 r90 top
R64 "RT0603FRE0710KL" FP-RT0603-MFG 76,53.5 r90 top value=10KΩ
R65 "CRCW0603330RFKEA" FP-CRCW0603-e3-MFG 99.25,66.65 r90 top
R66 "RT0603FRE0710KL" FP-RT0603-MFG 78,50 r270 top value=10KΩ
ST1 "PTH-M2D5X5" PTH-M2D5X5 103,116 r0 top
ST2 "PTH-M2D5X5" PTH-M2D5X5 109,116 r0 top
ST3 "PTH-M2D5X5" PTH-M2D5X5 115,116 r0 top
ST4 "PTH-M2D5X5" PTH-M2D5X5 24,116 r0 top
ST5 "PTH-M2D5X5" PTH-M2D5X5 30,116 r0 top
ST6 "PTH-M2D5X5" PTH-M2D5X5 36,116 r0 top
ST7 "PTH-M2D5X5" PTH-M2D5X5 103,101 r0 top
ST8 "PTH-M2D5X5" PTH-M2D5X5 109,101 r0 top
ST9 "PTH-M2D5X5" PTH-M2D5X5 115,101 r0 top
ST10 "PTH-M2D5X5" PTH-M2D5X5 24,98 r0 top
ST11 "PTH-M2D5X5" PTH-M2D5X5 103,82.5 r0 top
ST12 "PTH-M2D5X5" PTH-M2D5X5 109,82.5 r0 top
ST13 "PTH-M2D5X5" PTH-M2D5X5 115,82.5 r0 top
ST14 "PTH-M2D5X5" PTH-M2D5X5 30,70 r0 top
ST15 "PTH-M2D5X5" PTH-M2D5X5 110,69.9 r0 top
ST16 "PTH-M2D5X5" PTH-M2D5X5 25,25 r0 top
ST17 "PTH-M2D5X5" PTH-M2D5X5 115,25 r0 top
TP1 "5003" KSTN-5003 24,74.25 r0 top
TP2 "5003" KSTN-5003 45.75,22.75 r0 top
TP3 "5003" KSTN-5003 48.75,53.5 r0 top
TP4 "5003" KSTN-5003 82,38.5 r0 top
TP5 "5003" KSTN-5003 57.5,26.5 r0 top
TP6 "5003" KSTN-5003 64.5,39 r0 top
TP7 "5003" KSTN-5003 64.5,23.5 r0 top
TP8 "5003" KSTN-5003 82,26.5 r0 top
TP9 "5003" KSTN-5003 81.5,116.5 r0 top
TP10 "5003" KSTN-5003 57.25,108 r90 top
TP11 "5003" KSTN-5003 36.5,82.5 r90 top
TP12 "5003" KSTN-5003 51,95.5 r90 top
TP13 "5003" KSTN-5003 24,80 r90 top
TP14 "5003" KSTN-5003 24,85 r90 top
TP15 "5003" KSTN-5003 44,74.5 r90 top
TP16 "5003" KSTN-5003 80.5,96.5 r90 top
TP17 "5003" KSTN-5003 60,51.5 r90 top
TP18 "5003" KSTN-5003 112,55 r0 top
TP19 "5003" KSTN-5003 60,56.5 r90 top
TP20 "5003" KSTN-5003 108.5,49.5 r90 top
TP21 "5003" KSTN-5003 83.25,56.75 r90 top
TP22 "5003" KSTN-5003 78,43.75 r90 top
TP23 "5003" KSTN-5003 76.5,85.5 r90 top
TP24 "5003" KSTN-5003 76.5,89 r90 top
U1 "L78M05ABDT-TR" FP-L78M05ABDT-TR-MFG 37.307,45.95 r90 top
U2 "LM7812S/NOPB" FP-KTT0003B-MFG 40,33 r90 top
U3 "LTC3260MPMSE#PBF" LT-MSE-16-EDP_N 70,32.5 r180 top
U4 "REF3125AIDBZT" DBZ0003A_M 43.75,63.75 r90 top
U5 "TL072CD" FP-SO8-IPC_C 61.316,89.135 r0 top
U6 "TL072CD" FP-SO8-IPC_C 60.5,76 r0 top
U7 "LTC2050HVCS8#PBF" LT-S8-8_L 88.5,92.5 r0 top
U9 "LP339D" D0014A_L 71.375,53.23 r0 top

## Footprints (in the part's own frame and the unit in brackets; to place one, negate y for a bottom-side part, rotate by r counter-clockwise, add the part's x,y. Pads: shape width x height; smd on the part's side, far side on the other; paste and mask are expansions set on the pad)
CAPC1608X90X35ML15T15 [mm] "Chip Capacitor, 2-Leads, Body 1.60x0.81mm, IPC Low Density"
  rect 1.25x1.1 smd: 1(-0.85,0) 2(0.85,0)
  body extent -0.88,-0.48 0.87,0.48, height 0.9
D0014A_L [mm] "SOIC, 14-Leads, Body 8.75x4mm, Pitch 1.27mm, IPC High Density"
  rrect18% 1.25x0.55 smd: 1(-2.625,3.81) 2(-2.625,2.54) 3(-2.625,1.27) 4(-2.625,0) 5(-2.625,-1.27) 6(-2.625,-2.54) 7(-2.625,-3.81) 8(2.625,-3.81) 9(2.625,-2.54) 10(2.625,-1.27) 11(2.625,0) 12(2.625,1.27) 13(2.625,2.54) 14(2.625,3.81)
  silkscreen extent -2.75,-4.38 1.6,4.76, body extent -3.02,-4.32 3.02,4.32, height 1.59
DBZ0003A_M [mm] "SOT23, 3-Leads, Body 3.04x1.4mm, Pitch 0.95mm, IPC Low Density"
  rrect15% 1.2x0.65 smd: 1(-1.3,0.95) 2(-1.3,-0.95) 3(1.3,0)
  silkscreen extent -1.42,-1.5 0.7,1.95, body extent -1.26,-1.46 1.26,1.46, height 0.96
FP-0603-L_1_6_0_15-W_0_8-IPC_C [mm]
  rect 0.858x0.862 smd paste+0 mask+0: 1(-0.602,0) 2(0.602,0)
  silkscreen extent -1.03,-0.87 1.03,0.87, body extent -1.13,-0.58 1.13,0.58, height 0.25
FP-AC0603-MFG [mm]
  rect 0.9x0.8 smd paste+0 mask+0: 1(-0.85,0) 2(0.85,0)
  silkscreen extent -0.85,-0.82 0.85,0.82, body extent -1.4,-0.55 1.4,0.55, height 0.25
FP-BLM18-0_15-t0_8-IPC_C [mm]
  rect 0.906x0.858 smd paste+0 mask+0: 1(-0.576,0) 2(0.576,0)
  silkscreen extent -1.03,-0.87 1.03,0.87, body extent -1.13,-0.58 1.13,0.58, height 0.25
FP-C0603C-CF-MFG [mm]
  rect 0.75x0.9 smd paste+0 mask+0: 1(-0.6,0) 2(0.6,0)
  silkscreen extent -0.87,-0.85 0.88,0.85, body extent -1.2,-0.6 1.2,0.6, height 0.25
FP-C1608-080-0_1-IPC_A [mm]
  rect 1.331x1.012 smd paste+0 mask+0: 1(-0.741,0) 2(0.741,0)
  silkscreen extent -1.41,-0.91 1.41,0.91, body extent -1.91,-1.01 1.91,1.01, height 0.25
FP-C1608-080-0_1-MFG [mm]
  rect 0.7x0.7 smd paste+0 mask+0: 1(-0.7,0) 2(0.7,0)
  silkscreen extent -0.8,-0.75 0.8,0.75, body extent -1.15,-0.55 1.15,0.55, height 0.25
FP-CL10-IPC_A [mm]
  rect 1.158x1.012 smd paste+0 mask+0: 1(-0.827,0) 2(0.827,0)
  silkscreen extent -1.41,-0.91 1.41,0.91, body extent -1.91,-1.01 1.91,1.01, height 0.25
FP-CL10-IPC_C [mm]
  rect 0.758x0.812 smd paste+0 mask+0: 1(-0.627,0) 2(0.627,0)
  silkscreen extent -1.01,-0.85 1.01,0.85, body extent -1.11,-0.55 1.11,0.55, height 0.25
FP-CL21-IPC_C [mm]
  rect 1.055x1.356 smd paste+0 mask+0: 1(-0.726,0) 2(0.726,0)
  silkscreen extent -1.25,-1.12 1.25,1.12, body extent -1.35,-0.82 1.35,0.82, height 0.25
FP-CL31B106KBHNNNE-MFG [mm]
  rect 0.925x1.7 smd paste+0 mask+0: 1(-1.362,0) 2(1.362,0)
  silkscreen extent -0.53,-0.9 0.53,0.9, body extent -1.92,-1 1.92,1, height 0.25
FP-CRCW0603-e3-IPC_C [mm]
  rect 0.735x0.862 smd paste+0 mask+0: 1(-0.615,0) 2(0.615,0)
  silkscreen extent -0.75,-0.85 0.75,0.85, body extent -1.08,-0.58 1.08,0.58, height 0.25
FP-CRCW0603-e3-MFG [mm]
  rect 0.75x1 smd paste+0 mask+0: 1(-0.75,0) 2(0.75,0)
  silkscreen extent -0.8,-0.9 0.8,0.9, body extent -1.22,-0.6 1.22,0.6, height 0.25
FP-CRG0603-IPC_C [mm]
  rect 0.758x0.858 smd paste+0 mask+0: 1(-0.627,0) 2(0.627,0)
  silkscreen extent -1.01,-0.87 1.01,0.87, body extent -1.11,-0.58 1.11,0.58, height 0.25
FP-KTT0003B-MFG [mm]
  rect 1.07x2.16 smd paste+0 mask+0: 1(-2.54,-6.545) 2(0,-6.545) 3(2.54,-6.545)
  round 6.291 smd paste+0 mask+0: 4(0,4.13)
  Top Layer region: 5.4,7.625 -5.4,7.625 -5.4,5.715 -4.165,5.715 -4.165,0.635 4.165,0.635 4.165,5.715 5.4,5.715 5.4,7.625
  silkscreen extent -5.93,-5.59 5.21,0.26, body extent -5.5,-7.73 5.5,7.73, height 0.25
FP-L78M05ABDT-TR-MFG [mm]
  rect 1.6x3 smd paste+0 mask+0: 1(-2.3,-5.193) 3(2.3,-5.193)
  rect 6.7x6.7 smd paste+0 mask+0: 4(0,1.458)
  silkscreen extent -3.36,-3.11 3.36,-2.27, body extent -3.46,-6.79 3.46,4.91, height 0.25
FP-PG-TO247-3-MFG [mm]
  rect 2.8x2.8 hole 1.85 paste-1000 mask+0: 1(-0.228,5.46)
  round 2.8 hole 1.85 paste-1000 mask+0: 2(-0.228,0) 3(-0.228,-5.46)
  silkscreen extent -2.66,-8 2.66,8.56, body extent -2.76,-8.16 2.76,8.16, height 0.25
FP-RT0603-MFG [mm]
  rect 0.9x0.8 smd paste+0 mask+0: 1(-0.85,0) 2(0.85,0)
  silkscreen extent -0.85,-0.81 0.86,0.8, body extent -1.4,-0.55 1.4,0.55, height 0.25
FP-SO8-IPC_C [mm]
  rect 1.874x0.512 smd paste+0 mask+0: 1(-2.316,1.905)
  rrect100% 1.874x0.512 smd paste+0 mask+0: 2(-2.316,0.635) 3(-2.316,-0.635) 4(-2.316,-1.905) 5(2.316,-1.905) 6(2.316,-0.635) 7(2.316,0.635) 8(2.316,1.905)
  silkscreen extent -3.95,-2.45 0.88,2.45, body extent -3.35,-2.55 3.35,2.55, height 0.25
FP-SOD323-IPC_A [mm]
  rect 1.655x0.516 smd paste+0 mask+0: 1(-1.075,0)
  rrect100% 1.655x0.516 smd paste+0 mask+0: 2(1.075,0)
  silkscreen extent -1.75,-0.65 0.85,0.88
FP-SOT23-MFG#1 [mm]
  rect 0.7x0.6 smd paste-1000 mask+0: 1(-1,0.95) 2(-1,-0.95) 3(1,0)
  silkscreen extent -0.7,-1.5 0.7,1.5, body extent -1.5,-1.65 1.5,1.65, height 0.25
FP-SOT23-MFG#2 [mm]
  rect 0.9x0.8 smd paste+0 mask+0: 1(-1,0.95) 2(-1,-0.95) 3(1,0)
  silkscreen extent -0.18,-1.5 0.7,1.5, body extent -1.55,-1.6 1.55,1.6, height 0.25
FP-SOT-223-P008-MFG [mm]
  rect 1.5x1.2 smd paste+0 mask+0: 1(-3.2,2.3) 2(-3.2,0) 3(-3.2,-2.3)
  rect 1.5x3.3 smd paste+0 mask+0: 2(3.2,0)
  silkscreen extent -4.8,-3.35 1.85,3.35, body extent -4.05,-3.45 4.05,3.45, height 0.25
HDR1X3 [mm] "Connector; Header; 3 Position"
  rect 1.5x1.5 hole 0.9: 1(0,0)
  round 1.5 hole 0.9: 2(2.54,0) 3(5.08,0)
  silkscreen extent -1.27,-1.27 6.35,1.27
KSTN-5003 [mm] "Test Point, Through Hole, Dia 2.54mm"
  round 1.5 hole 1: 1(0,0)
  silkscreen extent -1.27,-1.27 1.27,1.27, body extent -1.27,-1.27 1.27,1.27, height 4.57
LT-MSE-16-EDP_N [mm] "SOP, 16-Leads, Body 4.1x3.1mm, Pitch 0.5mm, Thermal Pad 2.95x1.76mm, IPC Medium Density"
  oval 1.65x0.3 smd: 1(-2.075,1.75) 2(-2.075,1.25) 3(-2.075,0.75) 4(-2.075,0.25) 5(-2.075,-0.25) 6(-2.075,-0.75) 7(-2.075,-1.25) 8(-2.075,-1.75) 9(2.075,-1.75) 10(2.075,-1.25) 11(2.075,-0.75) 12(2.075,-0.25) 13(2.075,0.25) 14(2.075,0.75) 15(2.075,1.25) 16(2.075,1.75)
  rect 1.76x2.95 smd: 17(0,0)
  silkscreen extent -2.2,-2.08 0.85,2.57, body extent -1.55,-2.05 1.55,2.05, height 1.1
LT-S8-8_L [mm] "SOIC, 8-Leads, Body 4.9x3.9mm, Pitch 1.27mm, IPC High Density"
  oval 1.9x0.6 smd: 1(-2.35,1.905) 2(-2.35,0.635) 3(-2.35,-0.635) 4(-2.35,-1.905) 5(2.35,-1.905) 6(2.35,-0.635) 7(2.35,0.635) 8(2.35,1.905)
  silkscreen extent -2.47,-2.5 1,2.88, body extent -2,-2.5 2,2.5, height 1.76
ONSC-SOT-23-3-318-08_V [mm] "SOT23, 3-Leads, Body 2.92x1.3mm, Pitch 0.95mm"
  rect 0.9x0.8 smd: 1(-1,0.95) 2(-1,-0.95) 3(1,0)
  silkscreen extent -1.12,-1.46 0.65,2.03, body extent -0.65,-1.46 0.65,1.46, height 1.11
PTH-M2D5X5 [mm]
  round 5 hole 2.5: 1(0,0)
RESC0603(1608)_L [mm] "Chip Resistor, Body 1.6x0.8mm, IPC High Density"
  rrect25% 0.66x0.76 smd: 1(-0.7,0) 2(0.7,0)
  silkscreen extent 0,-0.3 0,0.3, body extent -0.8,-0.4 0.8,0.4, height 0.45
RESC1608X55X25ML10T15 [mm] "Chip Resistor, 2-Leads, Body 1.70x0.90mm, IPC Low Density"
  rect 0.8x1 smd: 1(-0.75,0) 2(0.75,0)
  body extent -0.85,-0.45 0.85,0.45, height 0.55
RESC1608X55X30ML20T20 [mm] "Chip Resistor, 2-Leads, Body 1.60x0.80mm, IPC Low Density"
  rect 1x1.1 smd: 1(-0.7,0) 2(0.7,0)
  body extent -0.9,-0.5 0.9,0.5, height 0.55
RESC1609X50X30ML10T20 [mm] "Chip Resistor, 2-Leads, Body 1.55x0.85mm, IPC Low Density"
  rect 0.9x1.05 smd: 1(-0.675,0) 2(0.675,0)
  body extent -0.82,-0.48 0.82,0.48, height 0.5
SAMS-C0603-2_M [mm] "Chip Capacitor, 2-Leads, Body 1.70x0.90mm, IPC Low Density"
  rect 0.95x1.05 smd: 1(-0.725,0) 2(0.725,0)
  body extent -0.85,-0.45 0.85,0.45, height 0.9
WSHM2818R0200FEA [mm]
  rect 3.5x5.1 smd: 1(-2.055,0) 2(2.055,0)
  silkscreen extent -4.06,-2.79 4.06,2.79

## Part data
C1 C6 C7 C14 C15 C18 C19 C23 C30 C31 C34 C37 C41 C42: library part CMP-2000-05332-1, "Multi-layer Ceramic Capacitor, -55 to 125 degC, 2-Pin SMD (0603), RoHS, Tape and Reel", Capacitance=0.1µF, Case Size/Dimension=0603, Dielectric=X7R, Manufacturer="Samsung Electro-Mechanics", Rated Voltage=50V, Tolerance (%)=±10%
C2 C4 C5 C9 C13 C16 C17: library part CMP-2000-07530-2, "CAP CER 10UF 50V X7R 1206", Capacitance=10uF, Manufacturer=Samsung, Temperature="-55°C to +125°C", Temperature Characteristic=X7R, Temperature Coefficient=15%, Temperature Range High=+125°C, Temperature Range Low=-55°C, Tolerance=10%, Voltage Rating=50V
C3 C8: library part CMP-13271-001433-1, "CL21 Series 0805 1uF 50V ±10% Tolerance X7R Multilayer Ceramic Chip Capacitor", Capacitance=1uF, Case Code (Imperial)=0805, Case Code (Metric)=2012, Dielectric=X7R, Max Operating Temperature=125°C, Min Operating Temperature=-55°C, Package Quantity=3000, Tolerance=10%, Voltage=50V
C10 C20 C36: library part CMP-2000-07531-4, "Ceramic Capacitor General Use 1uF ±10% 50V X7R 0603", Capacitance=1uF, Case Code (Imperial)=0603, Case Code (Metric)=1608, Dielectric=X7R, Max Operating Temperature=125°C, Min Operating Temperature=-55°C, Package Quantity=1, Tolerance=10%, Voltage Rating=50V
C11 C12 C22 C35 C38 C40: library part CMP-08246-006703-1, "Multilayer Ceramic Capacitors 10nF ±20% 50V X7R SMD 0603", Capacitance=10nF, Case Code (Imperial)=0603, Case Code (Metric)=1608, Dielectric=X7R, Dielectric Material=Ceramic, Max Operating Temperature=125°C, Min Operating Temperature=-55°C, Package Quantity=1, Tolerance=20%, Voltage Rating=50V
C21 C25 C27 C29 C39: library part CMP-2006-04410-1, Manufacturer="AVX Interconnect / Elco"
C24 C28: library part CMP-03020-010187-1, "C0603 47 pF X8R 30ppm/°C 20.00% 50 V", Capacitance="47 pF", Manufacturer=KEMET, Package=C0603C-CF, Temperature="-55°C to +125°C", Temperature Characteristic=X8R, Temperature Coefficient=30ppm/°C, Temperature Range High=+125°C, Temperature Range Low=-55°C, Tolerance=0.2, Voltage Rating="50 V"
C26: library part CMP-13271-001091-1, "Cap Ceramic 120pF 50V X7R ±10% Pad SMD 0603 +125°C T/R", Capacitance=120pF, Case Code (Imperial)=0603, Case Code (Metric)=1608, Dielectric=X7R, Max Operating Temperature=125°C, Min Operating Temperature=-55°C, Package Quantity=4000, Tolerance=10%, Voltage Rating=50V
C32 C33: library part CMP-13271-004548-1, "Cap Ceramic 1nF 50V X7R ±10% Pad SMD 0603 +125°C T/R", Capacitance=1nF, Case Code (Imperial)=0603, Case Code (Metric)=1608, Max Operating Temperature=125°C, Min Operating Temperature=-55°C, Ratings=AEC-Q200, Tolerance=10%, Voltage Rating=50V
D1: library part CMP-14400-000028-1, "DIODE ZENER 15V 250MW TO236AB"
D2 D3 D4 D5 D6 D7: library part CMP-14399-000012-1, "DIODE GEN PURP 100V 250MA SOD323"
FB1 FB3 FB4 FB5 FB6 FB7 FB8: library part CMP-06046-002563-1, "Chip Ferrite Bead, 0603, 60Ω @ 100MHz, 0.1Ω, , 1A", Case Code (Imperial)=0603, Case Code (Metric)=1608, Current Rating=500mA, DC Resistance (DCR)=100mR, Max Operating Temperature=125°C, Min Operating Temperature=-55°C, Package Quantity=4000, Ratings=AEC-Q200, Test Frequency=100MHz, Tolerance=25%
P1 P2 P3: "Header, 3-Pin"
Q1: library part CMP-32901-000198-1, "MOSFET N-CH 200V 30A TO-247AC", Case/Package=TO-247, Continuous Drain Current (ID)=30A, Drain to Source Breakdown Voltage=200V, Drain to Source Resistance=75mR, Gate to Source Voltage (Vgs)=20V, Input Capacitance=2.159nF, Max Operating Temperature=175°C, Max Power Dissipation=214W, Min Operating Temperature=-55°C
Q2: library part CMP-12195-000003-1, "TRANS NPN 80V 1A SOT-223", Collector Base Voltage=100V, Collector Emitter Breakdown Voltage=80V, Collector Emitter Saturation Voltage=0.5V, Emitter Base Voltage=5V, Manufacturer=STMicroelectronics, Max Collector Current=1A, Max Junction Temp=+150°C, Package=SOT-223-P008, Power Dissipation=1.6W, Temperature="to +150°C"
Q3 Q4 Q11: library part CMP-1048-00557-1, "High Voltage Transistor, PNP Silicon, 3-Pin SOT-23, Pb-Free, Tape and Reel", Manufacturer="On Semiconductor"
Q5 Q6 Q10 Q12 Q13: library part CMP-1048-00669-1, "High Voltage Transistor, NPN Silicon, 3-Pin SOT-23, Pb-Free, Tape and Reel", Manufacturer="On Semiconductor"
Q7: library part CMP-2000-04929-2, "MOSFET N-CH 60V 115MA SOT23-3", Case/Package=SOT-23, Continuous Drain Current (ID)=115mA, Drain to Source Breakdown Voltage=70V, Drain to Source Resistance=7.5R, Drain to Source Voltage (Vdss)=60V, Gate to Source Voltage (Vgs)=20V, Input Capacitance=50pF, Max Operating Temperature=150°C, Max Power Dissipation=300mW, Min Operating Temperature=-55°C, Package Quantity=3000, Power Dissipation=540mW, Threshold Voltage=2.5V
R: "Rezistory ke snímání proudu - SMD .02ohms 7watt 1%", Power=7W
R1 R4: library part CMP-009-00069-1, Case/Package=0603, Manufacturer=Rohm, Power=0.1W, Supplier Part Number 1=511-SFR03EZPJ274CT-ND, Tolerance=5%
R2 R3: library part CMP-009-00069-1, Case/Package=0603, Power=0.1W, Tolerance=5%
R5 R16 R19 R24 R32 R35 R38 R41 R45 R46 R56 R57 R59 R64 R66: library part CMP-03412-005349-1, "RES SMD 10K OHM 1% 1/10W 0603", Manufacturer=Yageo, Package=RT0603, Power Rating=0.1W, Resistance=10KΩ, Temperature="-55°C to +155°C", Temperature Coefficient="50 ppm/°C", Temperature Range High=+155°C, Temperature Range Low=-55°C, Tolerance=0.01, Voltage Rating=75V
R6: library part CMP-03412-013381-1, "RES 16.0K OHM 1/10W .5% SMD 0603", Manufacturer=Yageo, Package=RT0603, Power Rating=0.1W, Resistance=16KΩ, Temperature="-55°C to +155°C", Temperature Coefficient="50 ppm/°C", Temperature Range High=+155°C, Temperature Range Low=-55°C, Tolerance=0.005, Voltage Rating=75V
R7 R42 R60: library part CMP-03412-005349-1, "RES SMD 1K OHM 1% 1/10W 0603 Je tuspatny datasheet!!!", Case Code (Imperial)=0603, Case Code (Metric)=1608, Manufacturer=Yageo, Manufacturer Part Number=RT0603FRE0710KL, Max Operating Temperature=125°C, Max Power Dissipation=100mW, Min Operating Temperature=-55°C, Package=RT0603, Package Quantity=5000, Power Rating=0.1W, Resistance=1KΩ, Resistance Tolerance=1%, Resistor Type="Thin Film", Supplier Part Number 1=2693905, Temperature="-55°C to +155°C", Temperature Coefficient="50 ppm/°C", Temperature Range High=+155°C, Tolerance=0.01, Voltage Rating=75V
R8: library part CMP-2000-04630-2, "RES SMD 750 OHM 0.5% 1/10W 0603", Manufacturer=Yageo, Package=RT0603, Power Rating=0.1W, Resistance=750Ω, Temperature="-55°C to +155°C", Temperature Coefficient="50 ppm/°C", Temperature Range High=+155°C, Temperature Range Low=-55°C, Tolerance=0.005, Voltage Rating=75V
R9: library part CMP-03412-033768-1, "RES SMD 2.2K OHM 1% 1/10W 0603", Manufacturer=Yageo, Package=RT0603, Power Rating=0.1W, Resistance=2.2KΩ, Temperature="-55°C to +155°C", Temperature Coefficient="50 ppm/°C", Temperature Range High=+155°C, Temperature Range Low=-55°C, Tolerance=0.01, Voltage Rating=75V
R10: library part CMP-03412-033408-1, "RES SMD 10 OHM 1% 1/10W 0603", Manufacturer=Yageo, Package=RT0603, Power Rating=0.1W, Resistance=10Ω, Temperature="-55°C to +155°C", Temperature Coefficient="50 ppm/°C", Temperature Range High=+155°C, Temperature Range Low=-55°C, Tolerance=0.01, Voltage Rating=75V
R11 R12 R13 R34 R36: library part CMP-03412-006815-1, "RES SMD 220 OHM 1% 1/10W 0603", Manufacturer=Yageo, Package=RT0603, Power Rating=0.1W, Resistance=220Ω, Temperature="-55°C to +155°C", Temperature Coefficient="50 ppm/°C", Temperature Range High=+155°C, Temperature Range Low=-55°C, Tolerance=0.01, Voltage Rating=75V
R14: library part CMP-03412-022806-1, "RES SMD 100 OHM 1% 1/10W 0603", Manufacturer=Yageo, Package=RT0603, Power Rating=0.1W, Resistance=100Ω, Temperature="-55°C to +155°C", Temperature Coefficient="50 ppm/°C", Temperature Range High=+155°C, Temperature Range Low=-55°C, Tolerance=0.01, Voltage Rating=75V
R15 R20: library part CMP-03412-035774-1, "RES 470 OHM 1/10W 1% SMD 0603", Manufacturer=Yageo, Package=RT0603, Power Rating=0.1W, Resistance=470Ω, Temperature="-55°C to +155°C", Temperature Coefficient="50 ppm/°C", Temperature Range High=+155°C, Temperature Range Low=-55°C, Tolerance=0.01, Voltage Rating=75V
R17: library part CMP-2000-04770-2, "RES SMD 51K OHM 1% 1/10W 0603", Manufacturer=Yageo, Package=RT0603, Power Rating=0.1W, Resistance=51KΩ, Temperature="-55°C to +155°C", Temperature Coefficient="50 ppm/°C", Temperature Range High=+155°C, Temperature Range Low=-55°C, Tolerance=0.01, Voltage Rating=75V
R18 R30: library part CMP-2000-00123-1, Manufacturer=Panasonic
R21 R26: library part CMP-2000-04343-2, "RES 100K OHM 1/10W .1% SMD 0603", Manufacturer=Yageo, Package=RT0603, Power Rating=0.1W, Resistance=100KΩ, Temperature="-55°C to +155°C", Temperature Coefficient="25 ppm/°C", Temperature Range High=+155°C, Temperature Range Low=-55°C, Tolerance=0.001, Voltage Rating=75V
R22 R27: library part CMP-2000-04411-2, "RES 24.0K OHM 1/10W .1% SMD 0603", Manufacturer=Yageo, Package=RT0603, Power Rating=0.1W, Resistance=24KΩ, Temperature="-55°C to +155°C", Temperature Coefficient="25 ppm/°C", Temperature Range High=+155°C, Temperature Range Low=-55°C, Tolerance=0.001, Voltage Rating=75V
R23 R28 R39 R54 R55: library part CMP-2000-04423-2, "RES 2.20K OHM 1/10W .1% SMD 0603", Manufacturer=Yageo, Package=RT0603, Power Rating=0.1W, Resistance=2.2KΩ, Temperature="-55°C to +155°C", Temperature Coefficient="25 ppm/°C", Temperature Range High=+155°C, Temperature Range Low=-55°C, Tolerance=0.001, Voltage Rating=75V
R25: library part CMP-03412-026125-1, "RES SMD 1.8K OHM 1% 1/10W 0603", Manufacturer=Yageo, Package=RT0603, Power Rating=0.1W, Resistance=1.8KΩ, Temperature="-55°C to +155°C", Temperature Coefficient="50 ppm/°C", Temperature Range High=+155°C, Temperature Range Low=-55°C, Tolerance=0.01, Voltage Rating=75V
R29: library part CMP-03211-011415-1, "RES SMD 0 OHM JUMPER 1/10W 0603", Case Code (Imperial)=0603, Case Code (Metric)=1608, Max Operating Temperature=125°C, Max Power Dissipation=100mW, Min Operating Temperature=-55°C, Number of Resistors=1, Package Quantity=5000, Resistance=0mR, Resistor Type="Thick Film", Temperature Coefficient=100ppm/°C, Tolerance=0%, Voltage Rating=50V
R31: library part CMP-03412-005349-1, Manufacturer=Yageo, Manufacturer Part Number=RT0603FRE0710KL, Package=RT0603, Power Rating=0.1W, Temperature="-55°C to +155°C", Temperature Coefficient="50 ppm/°C", Temperature Range High=+155°C, Temperature Range Low=-55°C, Tolerance=0.01, Voltage Rating=75V
R33: library part CMP-03412-015060-1, "RES SMD 100K OHM 1% 1/10W 0603", Manufacturer=Yageo, Package=RT0603, Power Rating=0.1W, Resistance=100KΩ, Temperature="-55°C to +155°C", Temperature Coefficient="50 ppm/°C", Temperature Range High=+155°C, Temperature Range Low=-55°C, Tolerance=0.01, Voltage Rating=75V
R37 R44: library part CMP-03412-004734-2, "RES 976Ω 1.00% 0.1W 0603", Case Code (Imperial)=0603, Case Code (Metric)=1608, Max Operating Temperature=155°C, Max Power Dissipation=100mW, Min Operating Temperature=-55°C, Resistance=976R, Resistor Type="Thick Film", Temperature Coefficient=100ppm/°C, Tolerance=1%, Voltage Rating=50V
R40 R43: library part CMP-2000-03606-2, "RES Thick Film, 82Ω, 1%, 0.1W, 100ppm/°C, 0603", Case Code (Imperial)=0603, Case Code (Metric)=1608, Max Operating Temperature=155°C, Max Power Dissipation=100mW, Min Operating Temperature=-55°C, Package Quantity=10, Resistance=82R, Temperature Coefficient=100ppm/°C, Tolerance=1%, Voltage Rating=75V
R47 R58: library part CMP-03412-025080-2, "RES 5.1KΩ 1.00% 0.1W 0603", Case Code (Imperial)=0603, Case Code (Metric)=1608, Max Operating Temperature=155°C, Max Power Dissipation=100mW, Min Operating Temperature=-55°C, Ratings=AEC-Q200, Resistance=5.1kR, Resistor Type="Thick Film", Temperature Coefficient=100ppm/°C, Tolerance=1%, Voltage Rating=50V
